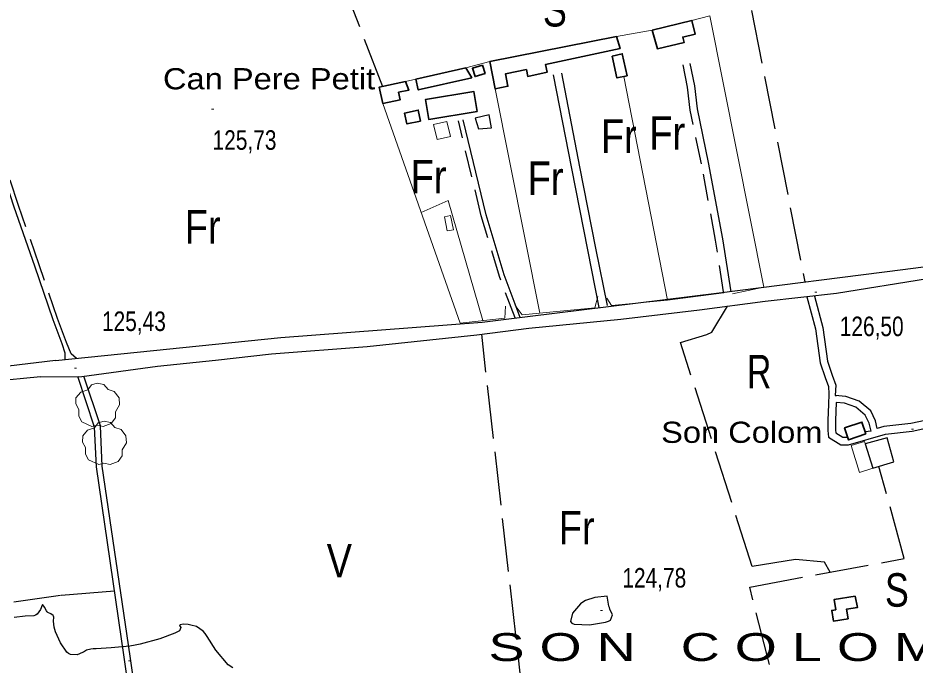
# Model space of a CAD drawing. Extents: x 483855 to 488461, y 4388206 to 4391419.
# Drawn here: x 484289 to 484690.9, y 4389628 to 4389918 of the extents above; entities that cross this region are included whole.
import ezdxf
from ezdxf.enums import TextEntityAlignment as Align

# ---------------------------------------------------------------- set-up
doc = ezdxf.new("R2010")
doc.units = 0
doc.header["$LTSCALE"] = 4
doc.linetypes.add('LONG_DASHED', pattern=[7.5, 6, -1.5])
doc.linetypes.add('MEDIUM_DASHED', pattern=[4.5, 3, -1.5])
for name, color, linetype, lineweight in [('21', 7, 'Continuous', 25), ('25', 7, 'LONG_DASHED', 25), ('29', 7, 'Continuous', 13), ('36', 7, 'Continuous', 25), ('38', 7, 'Continuous', 25), ('47', 7, 'Continuous', 35), ('51', 7, 'Continuous', 13), ('7', 7, 'Continuous', 13), ('8', 7, 'Continuous', 25)]:
    doc.layers.add(name, color=color, linetype=linetype, lineweight=lineweight)
doc.layers.add('31', color=7, linetype='Continuous')
doc.layers.add('5', color=7, linetype='Continuous')

msp = doc.modelspace()

# ---------------------------------------------------------------- linework, layer by layer
at = {"layer": '21'}
for points in [[(484495.28, 4389868.27), (484501.06, 4389868.73), (484500.07, 4389874.58), (484493.78, 4389873.15)], [(484671.89, 4389716.21), (484681.34, 4389719.15), (484678.32, 4389729.87), (484668.56, 4389727.13)]]:
    msp.add_lwpolyline(points, close=True, dxfattribs=at)
at = {"layer": '25'}
msp.add_line((484617.58, 4389921.3), (484641.49, 4389799.71), dxfattribs=at)
for points in [[(484604.22, 4389970.92), (484433.36, 4389936.58), (484452.31, 4389887.36)], [(484652.76, 4389669.66), (484650.28, 4389674.09), (484637.3, 4389675.34), (484617.95, 4389672.24), (484585.76, 4389772.55), (484597.53, 4389776.17), (484599.85, 4389777.23), (484606.9, 4389788.9)], [(484567.82, 4389412.68), (484536.28, 4389526.43), (484518.93, 4389580.48), (484496.71, 4389776.28)], [(484633.19, 4389599.18), (484616.77, 4389663.01), (484685.98, 4389675.8), (484674.66, 4389717.07)], [(484332.27, 4389661.18), (484308.02, 4389659.2), (484287.17, 4389656.17)]]:
    msp.add_lwpolyline(points, dxfattribs=at)
at = {"layer": '29'}
for points in [[(484322.12, 4389734.98), (484317.58, 4389737.1), (484316.17, 4389739.64), (484316.27, 4389742.62), (484314.9, 4389745.03), (484314.94, 4389747.78), (484317.1, 4389750.38), (484320.29, 4389751.38), (484321.94, 4389753.57), (484324.51, 4389754.4), (484327.37, 4389753.75), (484329.32, 4389751.48), (484332.13, 4389750.66), (484334.26, 4389747.81), (484334.5, 4389744.68), (484332.62, 4389741.53), (484332.62, 4389738.85), (484330.8, 4389736.24), (484327.18, 4389734.9), (484324.41, 4389735.53)], [(484325.15, 4389717.94), (484320.61, 4389720.06), (484319.2, 4389722.6), (484319.3, 4389725.58), (484317.93, 4389727.99), (484317.97, 4389730.74), (484320.13, 4389733.34), (484323.32, 4389734.34), (484324.97, 4389736.53), (484327.54, 4389737.36), (484330.4, 4389736.71), (484332.35, 4389734.44), (484335.16, 4389733.62), (484337.29, 4389730.77), (484337.53, 4389727.64), (484335.65, 4389724.49), (484335.65, 4389721.81), (484333.83, 4389719.2), (484330.21, 4389717.86), (484327.44, 4389718.49)], [(484325.15, 4389717.94), (484320.61, 4389720.06), (484319.2, 4389722.6), (484319.3, 4389725.58), (484317.93, 4389727.99), (484317.97, 4389730.74), (484320.13, 4389733.34), (484323.32, 4389734.34), (484324.97, 4389736.53), (484327.54, 4389737.36), (484330.4, 4389736.71), (484332.35, 4389734.44), (484335.16, 4389733.62), (484337.29, 4389730.77), (484337.53, 4389727.64), (484335.65, 4389724.49), (484335.65, 4389721.81), (484333.83, 4389719.2), (484330.21, 4389717.86), (484327.44, 4389718.49)]]:
    msp.add_lwpolyline(points, close=True, dxfattribs=at)
at = {"layer": '36'}
for points in [[(484517.17, 4389784.19), (484603.13, 4389794.82), (484685.32, 4389805.3), (484747.71, 4389813.3), (484758.15, 4389814.9), (484768.74, 4389814.74), (484778.42, 4389814.15), (484812.37, 4389809.26), (484830.33, 4389807.54), (484854.35, 4389807.87), (484873.69, 4389811.22), (484903.58, 4389815.06), (484917.42, 4389816.09)], [(484299.08, 4389757.16), (484317.53, 4389757.41), (484351.51, 4389761.97), (484377.46, 4389764.71), (484402.58, 4389767.45), (484445.48, 4389770.82), (484494.53, 4389776), (484517.86, 4389778.97), (484559.03, 4389783.09), (484594.28, 4389787.27), (484623.68, 4389791.07), (484655.71, 4389794.72), (484696.36, 4389801.24), (484736.4, 4389806.63), (484752.3, 4389808.91), (484759.43, 4389809.37), (484764.68, 4389809.45), (484780.66, 4389808.05), (484810.67, 4389804.88), (484820.05, 4389804.07), (484834.9, 4389802.84)], [(484305.72, 4389764.48), (484406.66, 4389774.86), (484496.92, 4389781.68), (484517.17, 4389784.19)], [(484305.72, 4389764.48), (484254.94, 4389758.35), (484205.13, 4389752.76), (484169.35, 4389749.49), (484137.59, 4389746.62), (484131.56, 4389746.5), (484124.49, 4389746.21), (484118.46, 4389745.51), (484112.63, 4389744.68)], [(484299.08, 4389757.16), (484256.2, 4389753.02), (484205.64, 4389747.3), (484169.85, 4389744.03), (484137.89, 4389741.14), (484131.73, 4389741.02), (484124.92, 4389740.74), (484119.16, 4389740.07), (484112.62, 4389739.14)]]:
    msp.add_lwpolyline(points, dxfattribs=at)
at = {"layer": '38'}
msp.add_line((484671.12, 4389732.84), (484668.56, 4389732.48), dxfattribs=at)
for points in [[(484310.01, 4389764.92), (484310.12, 4389765.27), (484310.16, 4389767.73), (484308.81, 4389771.99), (484304.75, 4389782.7), (484296.6, 4389806.79), (484287.34, 4389833.27), (484279.68, 4389856.31), (484271.74, 4389879.13), (484265.25, 4389901.03), (484256.53, 4389924.11)], [(484608.43, 4389795.27), (484604.73, 4389819.02), (484598.38, 4389853.29), (484593.39, 4389877.29), (484592.24, 4389887.56), (484590.13, 4389897.68)], [(484549.36, 4389788.31), (484544.25, 4389814.09), (484537.07, 4389850.61), (484528.89, 4389892.6)], [(484553, 4389789.1), (484547.91, 4389814.81), (484540.73, 4389851.32), (484532.56, 4389893.31)], [(484513.99, 4389783.8), (484506.79, 4389802.95), (484498.72, 4389829.87), (484488.45, 4389872.39)], [(484642.38, 4389793.03), (484646.2, 4389778.66), (484648.33, 4389763.52), (484650.51, 4389756.85), (484652.02, 4389752.79), (484652.18, 4389749.63), (484652.11, 4389744.76), (484651.82, 4389737.71), (484651.83, 4389733.13), (484652.06, 4389730.09), (484657.57, 4389726.68), (484661.06, 4389726.76), (484677.56, 4389731.52), (484689.56, 4389732.89), (484703.11, 4389735.76), (484706.27, 4389737.64), (484712.24, 4389737.27), (484714.66, 4389734.57), (484730.41, 4389726.64)], [(484645.82, 4389793.39), (484649.56, 4389779.34), (484651.67, 4389764.29), (484653.73, 4389757.98), (484655.41, 4389753.49), (484655.08, 4389748.84)], [(484489.18, 4389244.07), (484483.03, 4389242.11), (484480.26, 4389240.98), (484477.11, 4389240.3), (484475.31, 4389240.3), (484471.86, 4389241.04), (484469.6, 4389243.21), (484455.23, 4389272.52), (484425.47, 4389346.59), (484395.95, 4389421.03), (484367.7, 4389492.32), (484349.85, 4389537.97), (484349.16, 4389544.5), (484336.57, 4389631.64), (484324.12, 4389716.91), (484323.27, 4389734.69), (484315.74, 4389757.39)], [(484488.38, 4389246.58), (484482.13, 4389244.59), (484479.48, 4389243.51), (484476.83, 4389242.94), (484475.59, 4389242.94), (484473.15, 4389243.46), (484471.76, 4389244.79), (484457.64, 4389273.59), (484427.92, 4389347.57), (484398.4, 4389422), (484370.15, 4389493.29), (484352.44, 4389538.6), (484351.78, 4389544.83), (484339.18, 4389632.02), (484326.75, 4389717.16), (484325.89, 4389735.18), (484318.44, 4389757.53)], [(484673.95, 4389734.04), (484673.16, 4389737.44), (484671.01, 4389741.91), (484665.84, 4389746.24), (484659.88, 4389748.43), (484655.08, 4389748.84), (484655.65, 4389748.81)], [(484655.57, 4389745.75), (484655.24, 4389737.64), (484655.25, 4389733.26), (484655.34, 4389732.08), (484658.51, 4389730.12), (484660.54, 4389730.17), (484660.73, 4389729.92)], [(484671.12, 4389732.84), (484670.29, 4389736.43), (484668.57, 4389740.01), (484664.3, 4389743.58), (484659.22, 4389745.44), (484655.57, 4389745.75)], [(484731.95, 4389729.7), (484716.78, 4389737.33), (484713.85, 4389740.59), (484705.43, 4389741.12), (484701.85, 4389738.98), (484689.01, 4389736.27), (484676.88, 4389734.88), (484673.95, 4389734.04)]]:
    msp.add_lwpolyline(points, dxfattribs=at)
at = {"layer": '38', "linetype": 'MEDIUM_DASHED'}
for points in [[(484315.19, 4389765.45), (484312.88, 4389767.53), (484310.71, 4389772.65), (484306.64, 4389783.38), (484298.5, 4389807.44), (484289.24, 4389833.92), (484281.58, 4389856.96), (484273.65, 4389879.75), (484267.15, 4389901.67), (484258.45, 4389924.72)], [(484605.09, 4389795.26), (484601.48, 4389818.47), (484595.14, 4389852.65), (484590.13, 4389876.77), (484588.98, 4389887.04), (484586.9, 4389897.01)], [(484511.7, 4389783.68), (484504.65, 4389802.22), (484496.54, 4389829.28), (484486.26, 4389871.86)]]:
    msp.add_lwpolyline(points, dxfattribs=at)
at = {"layer": '47'}
for points in [[(484573.15, 4389912.51), (484590.92, 4389916.89), (484592.42, 4389910.78), (484586.8, 4389909.42), (484587.37, 4389907.02), (484575.46, 4389904.2)], [(484557.1, 4389909.71), (484500.33, 4389898.44), (484502.74, 4389886.26), (484508.49, 4389887.44), (484507.36, 4389892.93), (484516.73, 4389894.9), (484517.36, 4389891.86), (484526.03, 4389893.68), (484525.29, 4389897.16), (484558.73, 4389904.29)], [(484555.09, 4389900.93), (484557.27, 4389891.14), (484561.86, 4389892.16), (484559.68, 4389901.95)], [(484489.61, 4389895.72), (484467.19, 4389890.58), (484468.29, 4389885.75), (484492.29, 4389891.25)], [(484497.04, 4389896.86), (484498.2, 4389893.15), (484493.74, 4389891.75), (484492.58, 4389895.46)], [(484462.62, 4389889.6), (484450.84, 4389887.03), (484452.44, 4389879.68), (484460.22, 4389881.38), (484459.49, 4389884.7), (484464.08, 4389885.72)], [(484494.67, 4389876.07), (484473.03, 4389872.53), (484471.56, 4389881.51), (484493.2, 4389885.05)], [(484469.32, 4389871.83), (484463.24, 4389870.52), (484462.19, 4389875.42), (484468.27, 4389876.73)], [(484668.86, 4389731.58), (484661.06, 4389728.95), (484659.26, 4389734.27), (484667.06, 4389736.9)], [(484663.96, 4389658.89), (484654.58, 4389657.37), (484655.31, 4389652.82), (484653.5, 4389652.53), (484654.27, 4389647.7), (484660.82, 4389648.76), (484660.12, 4389653.03), (484665.14, 4389653.85)]]:
    msp.add_lwpolyline(points, close=True, dxfattribs=at)
at = {"layer": '47', "lineweight": 13}
for points in [[(484482.69, 4389864.88), (484476.7, 4389863.54), (484475.18, 4389870.34), (484481.17, 4389871.68)], [(484484.03, 4389823.1), (484482.76, 4389829.48), (484480.04, 4389828.94), (484481.31, 4389822.56)], [(484671.89, 4389716.21), (484668.22, 4389728.22), (484662.27, 4389726.4), (484665.94, 4389714.39)]]:
    msp.add_lwpolyline(points, close=True, dxfattribs=at)
at = {"layer": '51'}
for p, q in [((484573.15, 4389912.51), (484557.1, 4389909.71)), ((484500.33, 4389898.44), (484489.61, 4389895.72)), ((484560.33, 4389891.82), (484580.02, 4389791.6)), ((484467.19, 4389890.58), (484462.62, 4389889.6)), ((484502.74, 4389886.26), (484522.69, 4389785.73))]:
    msp.add_line(p, q, dxfattribs=at)
for points in [[(484609.05, 4389794.42), (484623.14, 4389797.37), (484598.87, 4389918.93), (484590.92, 4389916.89)], [(484452.44, 4389879.68), (484487.02, 4389781.24), (484507.12, 4389783.45), (484507.34, 4389788.85)], [(484469.61, 4389830.8), (484481.68, 4389836.15), (484497.25, 4389782.37)], [(484552.79, 4389792.45), (484554.9, 4389789.23), (484580.02, 4389791.6), (484605.15, 4389794.79)], [(484511.77, 4389789.09), (484514.92, 4389784.96), (484547.4, 4389788.17), (484548.67, 4389793.2)]]:
    msp.add_lwpolyline(points, dxfattribs=at)
at = {"layer": '7'}
for p, q in [((484375.65, 4389877.15), (484376.65, 4389877.15)), ((484645.91, 4389795.16), (484646.91, 4389795.16)), ((484314.25, 4389761.01), (484315.25, 4389761.01)), ((484689.21, 4389733.79), (484690.21, 4389733.79)), ((484549.9, 4389652.47), (484550.9, 4389652.47)), ((484338.54, 4389629.85), (484339.54, 4389629.85))]:
    msp.add_line(p, q, dxfattribs=at)
at = {"layer": '8'}
msp.add_lwpolyline([(484552.89, 4389658.83), (484547.34, 4389658.25), (484543.17, 4389656.92), (484542.08, 4389656.24), (484541.02, 4389655.43), (484537.41, 4389651.35), (484536.48, 4389647.52), (484537.1, 4389646.86), (484538.11, 4389646.37), (484544.96, 4389646.03), (484552.23, 4389647.2), (484553.5, 4389647.66), (484554.46, 4389648.18), (484555.25, 4389650.54), (484554.16, 4389653.11), (484553.93, 4389653.76), (484553.72, 4389654.39)], close=True, dxfattribs=at)
msp.add_lwpolyline([(484385.23, 4389626.73), (484383.17, 4389628.15), (484377.59, 4389634.65), (484373.75, 4389640.89), (484372.79, 4389642.15), (484371.88, 4389643.2), (484368.98, 4389645.32), (484366.47, 4389645.96), (484365.81, 4389646.08), (484365.17, 4389646.18), (484362.99, 4389646.34), (484361.58, 4389646.12), (484361.42, 4389645.98), (484361.37, 4389645.81), (484362.01, 4389644.89), (484361.35, 4389643.41), (484360.46, 4389642.88), (484359.28, 4389642.3), (484352.47, 4389639.76), (484343.79, 4389637.38), (484341.42, 4389636.9), (484339.07, 4389636.5), (484330.71, 4389635.69), (484323.99, 4389635.36), (484322.68, 4389635.25), (484321.6, 4389635.14), (484319.7, 4389634.69), (484318.83, 4389634.07), (484318.4, 4389633.85), (484317.9, 4389633.61), (484315.43, 4389632.56), (484312.48, 4389632.69), (484311.67, 4389633.18), (484310.87, 4389633.87), (484308.02, 4389638.04), (484305.83, 4389642.85), (484305.45, 4389643.95), (484305.17, 4389644.95), (484304.94, 4389647.73), (484304.99, 4389649.51), (484304.87, 4389649.88), (484304.71, 4389650.2), (484303.65, 4389650.92), (484302.36, 4389651.63), (484302.06, 4389651.94), (484301.77, 4389652.29), (484300.91, 4389654), (484300.18, 4389655.08), (484299.98, 4389655.05), (484299.78, 4389654.87), (484299.04, 4389653), (484297.54, 4389650.8), (484296.86, 4389650.42), (484296.07, 4389650.12), (484292.24, 4389649.87), (484287.31, 4389649.38)], dxfattribs=at)

# ---------------------------------------------------------------- texts
at = {"layer": '31'}
for s, width, p in [('S', 0.8, (484529.51, 4389914.2)), ('Fr', 0.85, (484558.15, 4389857.58)), ('Fr', 0.85, (484579.81, 4389858.97)), ('Fr', 0.85, (484472.91, 4389839.4)), ('Fr', 0.85, (484525.31, 4389838.7)), ('Fr', 0.85, (484371.73, 4389816.94)), ('R', 0.75, (484621.03, 4389752.02)), ('Fr', 0.85, (484539.28, 4389682.12)), ('V', 0.85, (484432.95, 4389667.34)), ('S', 0.8, (484682.72, 4389654.18))]:
    msp.add_text(s, height=15, dxfattribs=dict(at, width=width)).set_placement(p, align=Align.CENTER)
at = {"layer": '5', "width": 1.15}
for s, p in [('Can Pere Petit', (484448.96, 4389886.03)), ('Son Colom', (484649.36, 4389727.6))]:
    msp.add_text(s, height=9.5, dxfattribs=at).set_placement(p, align=Align.RIGHT)
at = {"layer": '5', "width": 1.45}
msp.add_text('S O N   C O L O M', height=12.49, dxfattribs=at).set_placement((484499.75, 4389629.85))
at = {"layer": '7', "width": 0.8}
for s, p in [('125,73', (484376.15, 4389858.95)), ('125,43', (484326.6, 4389777.73)), ('126,50', (484657.11, 4389775.44)), ('124,78', (484559.71, 4389662.76))]:
    msp.add_text(s, height=8.75, dxfattribs=at).set_placement(p)

doc.saveas('drawing.dxf')
